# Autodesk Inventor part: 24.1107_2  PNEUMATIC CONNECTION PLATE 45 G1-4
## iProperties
Created: 2007-01
Part Number: 24.1107_2  PNEUMATIC CONNECTION PLATE 45 G1-4
Document SubType Name: Modeling
Designer: Andy Moles
Material: Aluminum-6061
Mass: 149.973 g
Surface Area: 129.877 cm^2
Volume: 55.3405 cm^3
Density: 2.71 g/cm^3
Author: Andy Moles
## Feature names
1. Extrusion1
2. Hole1
3. Hole2
4. Fillet1
5. Revolution1
6. Extrusion2
7. Chamfer1
